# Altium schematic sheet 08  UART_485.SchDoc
size 246 x 182 mm
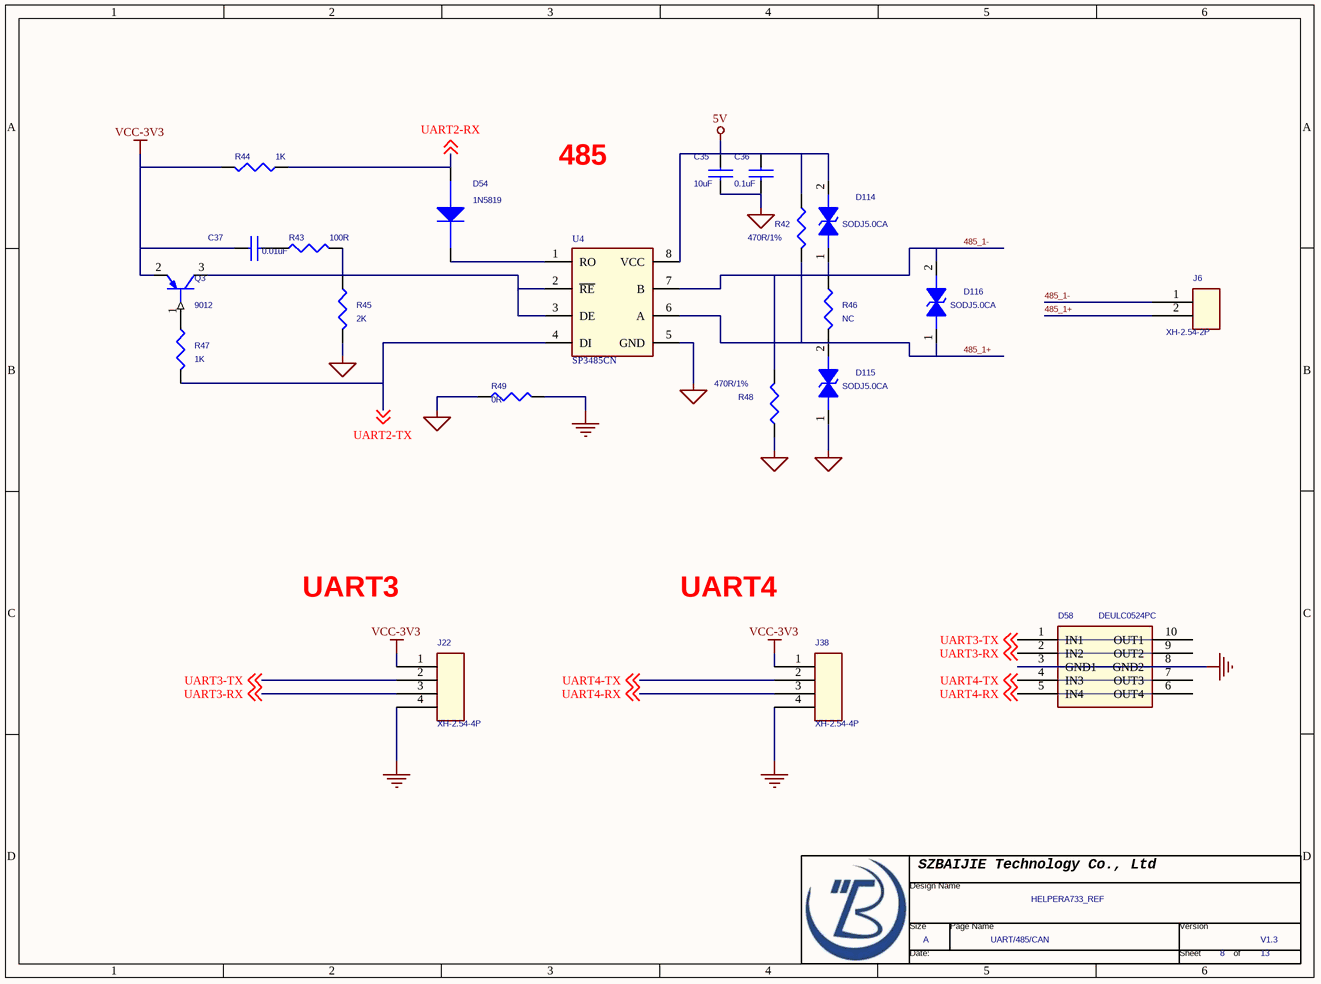
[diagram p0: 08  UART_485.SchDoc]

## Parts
*  Page Count: 13  Page Number: 8  Page Size: A  Title: HELPERA733_REF  RevCode: V1.3  Doc: UART/485/CAN  (hidden comment: TitleBlock0-BJ)  (graphical)
C35  10uF  [C0603]
C36  0.1uF  [C0402]
C37  0.01uF  [C0402]
D54  1N5819  [SOD323]
D58  DEULC0524PC  [RCLAMP0524P]
D114  SODJ5.0CA  [R0402]
D115  SODJ5.0CA  [R0402]
D116  SODJ5.0CA  [R0402]
J6  XH-2.54-2P  [XH-2.54-2P]
J22  XH-2.54-4P  [XH-2.54-4P]
J38  XH-2.54-4P  [XH-2.54-4P]
Q3  9012  [SOT23]
R42  470R/1%  [R0402]
R43  100R  [R0402]
R44  1K  [R0402]
R45  2K  [R0402]
R46  NC  [R0402]
R47  1K  [R0402]
R48  470R/1%  [R0402]
R49  0R  [R0402]
U4  SP3485CN  [SO8]

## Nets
5V: C35.1 C36.1 D114.2(CATHODE) R42.1 U4.8(VCC)
GND: D58.3(GND1) D58.8(GND2) J22.4 J38.4 R49.2
GND_485: C35.2 C36.2 D115.1(ANODE) R45.2 R48.1 R49.1 U4.5(GND)
VCC-3V3: C37.1 J22.1 J38.1 Q3.2(EMITTER) R44.2
485_1+: D115.2(CATHODE) D116.1(ANODE) J6.2 R42.2 R46.2 U4.6(A)
485_1-: D114.1(ANODE) D116.2(CATHODE) J6.1 R46.1 R48.2 U4.7(B)
UART2-RX: D54.1(ANODE) R44.1 ; off-sheet UART2-RX
UART2-TX: R47.2 U4.4(DI) ; off-sheet UART2-TX
UART3-RX: D58.2(IN2) D58.9(OUT2) J22.3 ; off-sheet UART3-RX
UART3-TX: D58.1(IN1) D58.10(OUT1) J22.2 ; off-sheet UART3-TX
UART4-RX: D58.5(IN4) D58.6(OUT4) J38.3 ; off-sheet UART4-RX
UART4-TX: D58.4(IN3) D58.7(OUT3) J38.2 ; off-sheet UART4-TX
NetC37_2: C37.2 R43.1
NetD54_2: D54.2(CATHODE) U4.1(RO)
NetQ3_1: Q3.1(BASE) R47.1
NetQ3_3: Q3.3(COLLECTOR) R43.2 R45.1 U4.2(~{RE}) U4.3(DE)

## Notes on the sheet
- 485
- UART3
- UART4

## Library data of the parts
C35 = C0603
C36 C37 = C0402
D54 = BAS21/SOT_1
D58 = rRClamp0524P
D114-D116 = ESD_DIODE: TVS diode;DC Working Voltage(VDC):16.0V;Clamping Voltage(VCL)Ipeak = 1A,8/20s:290V Maximum;Capacitance(C)@1MHz, 1V:2pF Typic; Part Name: CDS2C16GTH; Brand: EPCOS稲炊吹
J6 = CON4_3_Dup1
J22 J38 = CON4
Q3 = 2N3906_0
R42-R49 = R0402
U4 = SP3485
